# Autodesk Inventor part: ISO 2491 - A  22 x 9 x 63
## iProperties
IsCustomPart: 0
Created: 2009-02
Part Number: ISO 2491 - A  22 x 9 x 63
Material: Steel, Mild
Description: Thin parallel keys
Document SubType Name: Modeling
Standard: ISO 2491
Designer: 904Chiaki
Standard Revision: First edition 1974-08-15
Standards Organization: ISO
Language: en-US
Size Designation: A  22 x 9 x 63
Categories: <MemberInstance><Categories><Category DisplayName="Shaft Parts" InternalName="7f7aeb1f-a693-4053-b835-cee3144e0d98" Mnemonic="SHFT"><Category DisplayName="Keys"
Density: 1 g/cm^3
Author: 904Chiaki
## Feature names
1. Body1 [Extrusion]
2. Chamfer1
